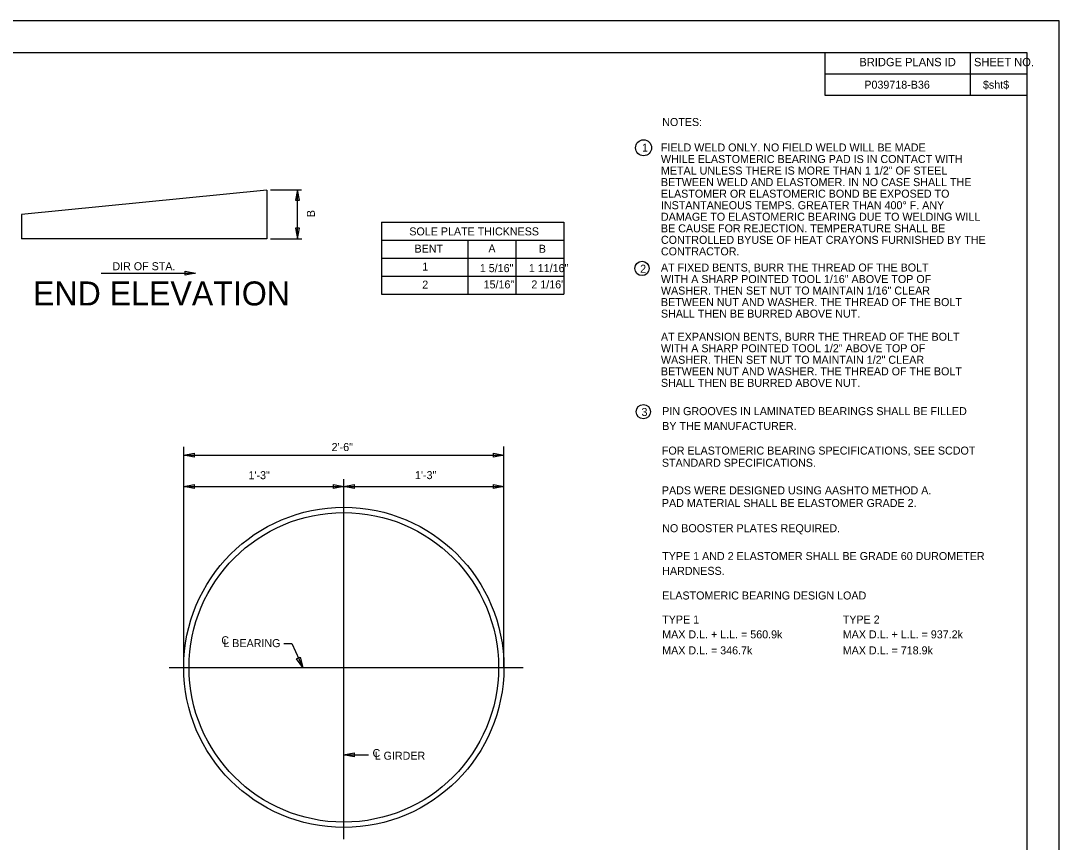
# Model space of a CAD drawing. Extents: x -125.5 to -89.4, y -5.1 to 16.9.
# Drawn here: x -105.75 to -89.53, y 4.11 to 16.93 of the extents above; entities that cross this region are included whole.
import ezdxf

# ---------------------------------------------------------------- set-up
doc = ezdxf.new("R2010")
doc.units = 0
for name, color, linetype in [('BR_AUTO DIMENSION', 7, 'Continuous'), ('BR_BORDER LINES', 7, 'Continuous'), ('BR_CENTER LINES', 7, 'Continuous'), ('BR_STRUCTURAL STEEL', 7, 'Continuous'), ('BR_TABLE LINES', 7, 'Continuous'), ('BR_TEXT', 7, 'Continuous'), ('Level 31', 7, 'Continuous')]:
    doc.layers.add(name, color=color, linetype=linetype)

msp = doc.modelspace()

# ---------------------------------------------------------------- linework, layer by layer
at = {"layer": 'BR_AUTO DIMENSION'}
for p, q in [((-101.846, 14.295), (-101.364, 14.295)), ((-101.427, 13.53), (-101.427, 14.295)), ((-101.846, 13.53), (-101.358, 13.53)), ((-104.495, 12.991), (-103.02, 12.991)), ((-103.204, 8.349), (-103.204, 10.278)), ((-98.204, 8.349), (-98.204, 10.283)), ((-103.204, 10.151), (-98.204, 10.151)), ((-103.204, 9.661), (-98.204, 9.661)), ((-103.204, 6.836), (-103.204, 8.77)), ((-98.204, 6.836), (-98.204, 8.77)), ((-101.638, 7.207), (-101.513, 7.207)), ((-101.513, 7.207), (-101.344, 6.836)), ((-100.706, 5.469), (-100.316, 5.469))]:
    msp.add_line(p, q, dxfattribs=at)
for points in [[(-101.396, 14.132), (-101.427, 14.295), (-101.458, 14.132)], [(-101.458, 13.693), (-101.427, 13.53), (-101.396, 13.693)], [(-103.183, 13.022), (-103.02, 12.991), (-103.183, 12.96)], [(-103.042, 10.12), (-103.204, 10.151), (-103.042, 10.182)], [(-98.367, 10.182), (-98.204, 10.151), (-98.367, 10.12)], [(-103.042, 9.63), (-103.204, 9.661), (-103.042, 9.693)], [(-100.867, 9.693), (-100.704, 9.661), (-100.867, 9.63)], [(-100.542, 9.63), (-100.704, 9.661), (-100.542, 9.693)], [(-98.367, 9.693), (-98.204, 9.661), (-98.367, 9.63)], [(-101.383, 6.996), (-101.344, 6.836), (-101.44, 6.971)], [(-100.543, 5.438), (-100.706, 5.469), (-100.543, 5.501)]]:
    msp.add_lwpolyline(points, close=True, dxfattribs=at)
for centre, radius in [((-96.023, 14.95), 0.125), ((-96.047, 13.066), 0.112), ((-96.026, 10.829), 0.112)]:
    msp.add_circle(centre, radius, dxfattribs=at)
at = {"layer": 'BR_BORDER LINES'}
for p, q in [((-90.033, 16.434), (-123.699, 16.434)), ((-93.186, 15.767), (-93.186, 16.434)), ((-90.919, 15.767), (-90.919, 16.434)), ((-90.033, -4.566), (-90.033, 16.434)), ((-93.186, 16.104), (-90.033, 16.104)), ((-90.919, 16.104), (-90.033, 16.104)), ((-90.033, 15.767), (-93.186, 15.767))]:
    msp.add_line(p, q, dxfattribs=at)
at = {"layer": 'BR_CENTER LINES'}
for p, q in [((-100.704, 4.152), (-100.704, 9.777)), ((-103.432, 6.836), (-97.902, 6.836))]:
    msp.add_line(p, q, dxfattribs=at)
at = {"layer": 'BR_STRUCTURAL STEEL'}
for p, q in [((-101.906, 14.291), (-105.739, 13.91)), ((-101.906, 14.291), (-101.906, 13.91)), ((-105.739, 13.91), (-105.739, 13.53)), ((-101.906, 13.91), (-101.906, 13.53)), ((-101.906, 13.53), (-105.739, 13.53))]:
    msp.add_line(p, q, dxfattribs=at)
for radius in [2.5, 2.417]:
    msp.add_circle((-100.704, 6.836), radius, dxfattribs=at)
at = {"layer": 'BR_TABLE LINES'}
for p, q in [((-100.116, 13.788), (-97.269, 13.788)), ((-100.116, 13.788), (-100.116, 12.663)), ((-97.269, 13.788), (-97.269, 12.663)), ((-100.116, 13.507), (-97.269, 13.507)), ((-98.769, 13.507), (-98.769, 12.663)), ((-98.019, 13.507), (-98.019, 12.663)), ((-100.116, 13.225), (-97.269, 13.225)), ((-100.116, 12.944), (-97.269, 12.944)), ((-100.116, 12.663), (-97.269, 12.663))]:
    msp.add_line(p, q, dxfattribs=at)
at = {"layer": 'Level 31'}
msp.add_lwpolyline([(-125.533, -5.066), (-89.533, -5.066), (-89.533, 16.934), (-125.533, 16.934)], close=True, dxfattribs=at)

# ---------------------------------------------------------------- texts
at = {"layer": 'BR_TEXT'}
for s, height, p in [('BRIDGE PLANS ID', 0.13, (-92.654, 16.224)), ('SHEET NO.', 0.13, (-90.864, 16.224)), ('P039718-B36', 0.125, (-92.576, 15.873)), ('$sht$', 0.125, (-90.724, 15.873)), ('NOTES:', 0.125, (-95.732, 15.29)), ('1', 0.125, (-96.047, 14.89)), ('FIELD WELD ONLY. NO FIELD WELD WILL BE MADE ', 0.125, (-95.752, 14.893)), ('WHILE ELASTOMERIC BEARING PAD IS IN CONTACT WITH ', 0.125, (-95.752, 14.712)), ('METAL UNLESS THERE IS MORE THAN 1 1/2" OF STEEL ', 0.125, (-95.752, 14.532)), ('BETWEEN WELD AND ELASTOMER. IN NO CASE SHALL THE ', 0.125, (-95.752, 14.352)), ('ELASTOMER OR ELASTOMERIC BOND BE EXPOSED TO ', 0.125, (-95.752, 14.171)), ('INSTANTANEOUS TEMPS. GREATER THAN 400%%d F. ANY ', 0.125, (-95.752, 13.991)), ('DAMAGE TO ELASTOMERIC BEARING DUE TO WELDING WILL ', 0.125, (-95.752, 13.811)), ('SOLE PLATE THICKNESS', 0.125, (-99.681, 13.582)), ('BE CAUSE FOR REJECTION. TEMPERATURE SHALL BE ', 0.125, (-95.752, 13.63)), ('CONTROLLED BYUSE OF HEAT CRAYONS FURNISHED BY THE ', 0.125, (-95.752, 13.45)), ('BENT', 0.125, (-99.6, 13.313)), ('A', 0.125, (-98.446, 13.315)), ('B', 0.125, (-97.659, 13.311)), ('CONTRACTOR.', 0.125, (-95.752, 13.27)), ('DIR OF STA.', 0.125, (-104.317, 13.038)), ('1', 0.125, (-99.479, 13.032)), ('1 5/16"', 0.125, (-98.58, 13.008)), ('1 11/16"', 0.125, (-97.815, 13.008)), ('AT FIXED BENTS, BURR THE THREAD OF THE BOLT', 0.125, (-95.752, 13.018)), ('2', 0.125, (-96.076, 12.999)), ('END ELEVATION', 0.375, (-105.557, 12.488)), ('2', 0.125, (-99.479, 12.751)), ('15/16"', 0.125, (-98.521, 12.754)), ('2 1/16"', 0.125, (-97.775, 12.754)), ('WITH A SHARP POINTED TOOL 1/16" ABOVE TOP OF', 0.125, (-95.752, 12.838)), ('WASHER. THEN SET NUT TO MAINTAIN 1/16" CLEAR', 0.125, (-95.752, 12.658)), ('BETWEEN NUT AND WASHER. THE THREAD OF THE BOLT', 0.125, (-95.752, 12.478)), ('SHALL THEN BE BURRED ABOVE NUT.', 0.125, (-95.752, 12.298)), ('AT EXPANSION BENTS, BURR THE THREAD OF THE BOLT', 0.125, (-95.752, 11.937)), ('WITH A SHARP POINTED TOOL 1/2" ABOVE TOP OF', 0.125, (-95.752, 11.757)), ('WASHER. THEN SET NUT TO MAINTAIN 1/2" CLEAR', 0.125, (-95.752, 11.577)), ('BETWEEN NUT AND WASHER. THE THREAD OF THE BOLT', 0.125, (-95.752, 11.397)), ('SHALL THEN BE BURRED ABOVE NUT.', 0.125, (-95.752, 11.217)), ('3', 0.125, (-96.055, 10.762)), ('PIN GROOVES IN LAMINATED BEARINGS SHALL BE FILLED', 0.125, (-95.732, 10.775)), ('BY THE MANUFACTURER.', 0.125, (-95.732, 10.543)), ('2\'-6"', 0.125, (-100.894, 10.214)), ('FOR ELASTOMERIC BEARING SPECIFICATIONS, SEE SCDOT', 0.125, (-95.737, 10.159)), ('STANDARD SPECIFICATIONS.', 0.125, (-95.737, 9.969)), ('1\'-3"', 0.125, (-102.192, 9.775)), ('1\'-3"', 0.125, (-99.592, 9.776)), ('PADS WERE DESIGNED USING AASHTO METHOD A.', 0.125, (-95.737, 9.538)), ('PAD MATERIAL SHALL BE ELASTOMER GRADE 2.', 0.125, (-95.737, 9.34)), ('NO BOOSTER PLATES REQUIRED.', 0.125, (-95.732, 8.947)), ('TYPE 1 AND 2 ELASTOMER SHALL BE GRADE 60 DUROMETER', 0.125, (-95.732, 8.512)), ('HARDNESS.', 0.125, (-95.732, 8.281)), ('ELASTOMERIC BEARING DESIGN LOAD', 0.125, (-95.732, 7.896)), ('TYPE 1', 0.125, (-95.732, 7.521)), ('TYPE 2', 0.125, (-92.913, 7.521)), ('MAX D.L. + L.L. = 560.9k', 0.125, (-95.732, 7.289)), ('MAX D.L. + L.L. = 937.2k', 0.125, (-92.913, 7.289)), ('MAX D.L. = 346.7k', 0.125, (-95.732, 7.039)), ('MAX D.L. = 718.9k', 0.125, (-92.913, 7.039)), ('C', 0.125, (-100.255, 5.435)), ('L GIRDER', 0.125, (-100.222, 5.394))]:
    msp.add_text(s, height=height, dxfattribs=at).set_placement(p)
for s, rotation, p in [('B', 90, (-101.156, 13.868)), ('C', 360, (-102.616, 7.197)), ('L BEARING', 360, (-102.585, 7.152))]:
    msp.add_text(s, height=0.125, rotation=rotation, dxfattribs=at).set_placement(p)

doc.saveas('drawing.dxf')
